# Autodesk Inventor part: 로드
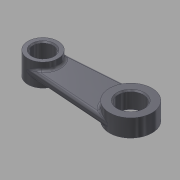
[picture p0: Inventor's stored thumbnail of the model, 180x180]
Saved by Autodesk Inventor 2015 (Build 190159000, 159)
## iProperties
Created: 2015-10
Part Number: 로드
Document SubType Name: Modeling
Designer: mdu
Density: 7.86 g/cm^3
Material: 강철, 연강
Mass: 20.3761 g
Surface Area: 22.2266 cm^2
Volume: 2.59237 cm^3
Appearance: 강철 - 광택
Author: mdu
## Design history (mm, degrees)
sketch "스케치1"
  geometry: L1 (13.821, 5.985)-(48.643, 8.478); L2 (48.643, -8.478)-(13.821, -5.985); C1 r 4 at (14.25, 0) reference; A1 r 6 centre (14.25, 0) between (13.821, 5.985) and (13.821, -5.985); A2 r 8.5 centre (49.25, 0) between (48.643, 8.478) and (48.643, -8.478); 1 further point
  constraints: 4 end point, 4 point on circle, 4 tangent, 2 centre point, 1 coincident, 1 horizontal alignment
  dimensions: "d0" = 12 diameter of A1; "d1" = 35 distance of A2.centre A1.centre; "d2" = 17 diameter of A2
  node "참조1"
extrude "돌출1" new body sketch "스케치1" distance "d3" = 9; taper "d4" = 0 deg
node "작업 평면1"
node "작업 평면2"
extrude "돌출2" join sketch "스케치1" stored distance "d7" = 10; taper "d8" = 0 deg
node "작업 평면3"
extrude "돌출3" join sketch "스케치1" stored distance "d10" = 10; taper "d11" = 0 deg
hole "구멍1" diameter "d14" = 10; stored, may be unused: countersink angle "d18" = 90 deg, drill point angle "d20" = 118 deg; dims "d12" = 10, "d13" = 10, "d15" = 6, "d16" = 4, "d17" = 2, "d19" = 8
fillet "모깎기1" dims "d21" = 1
chamfer "모따기1" distance "d22" = 0.5; stored, may be unused: second distance "d23" = 2, angle "d24" = 45 deg
chamfer "모따기2" distance "d25" = 0.5; stored, may be unused: second distance "d26" = 2, angle "d27" = 45 deg
node "솔리드1"
other parameters: "d5" = -6, "d6" = -3, "d9" = -4
